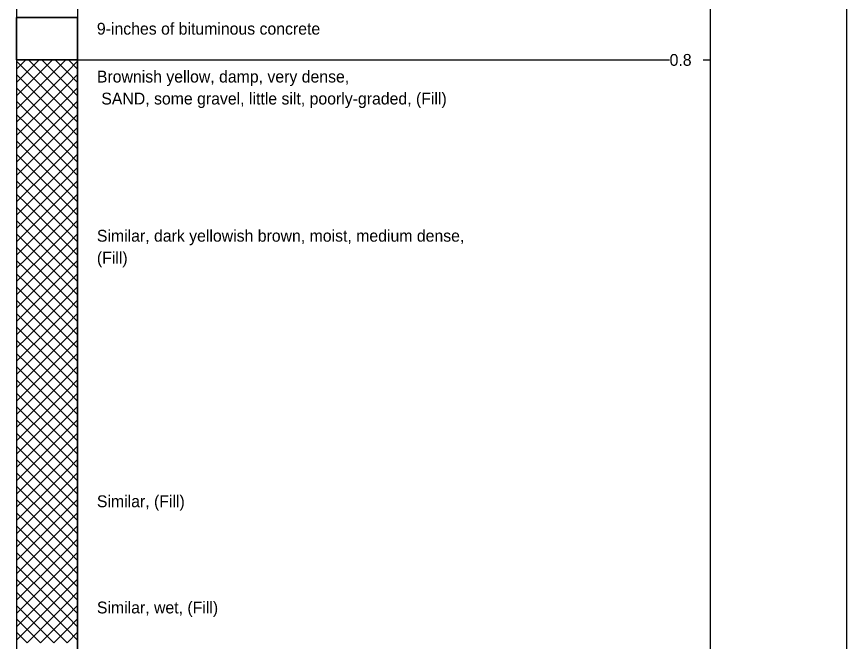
# Model space of a CAD drawing. Extents: x 9422 to 9552, y 6780 to 6860.
# Drawn here: x 9438.31 to 9453.95, y 6835.26 to 6847.03 of the extents above; entities that cross this region are included whole.
import ezdxf

# ---------------------------------------------------------------- set-up
doc = ezdxf.new("R2010")
doc.units = 0
doc.layers.add('7', color=7, linetype='Continuous')
doc.layers.add('8', color=7, linetype='Continuous')

msp = doc.modelspace()

# ---------------------------------------------------------------- linework, layer by layer
at = {"layer": '7'}
for p, q in [((9438.314, 6847.011), (9438.314, 6846.211)), ((9439.463, 6847.011), (9438.314, 6847.011)), ((9439.463, 6846.211), (9439.463, 6847.011)), ((9438.314, 6846.211), (9439.463, 6846.211)), ((9438.314, 6846.211), (9438.314, 6834.011)), ((9439.463, 6846.211), (9438.314, 6846.211)), ((9439.463, 6834.011), (9439.463, 6846.211)), ((9439.463, 6846.211), (9450.615, 6846.211)), ((9451.244, 6846.211), (9451.38, 6846.211))]:
    msp.add_line(p, q, dxfattribs=at)
for points in [[(9453.945, 6860.114), (9453.945, 6821.983)], [(9438.314, 6850.528), (9438.314, 6821.983)], [(9439.463, 6850.528), (9439.463, 6821.983)], [(9451.38, 6850.528), (9451.38, 6821.983)]]:
    msp.add_lwpolyline(points, dxfattribs=at)
at = {"layer": '8'}
for p, q in [((9438.314, 6846.036), (9438.489, 6846.211)), ((9438.514, 6845.986), (9438.314, 6846.185)), ((9438.514, 6845.986), (9438.739, 6846.211)), ((9438.764, 6845.986), (9438.539, 6846.211)), ((9438.764, 6845.986), (9438.989, 6846.211)), ((9439.014, 6845.986), (9438.789, 6846.211)), ((9439.014, 6845.986), (9439.239, 6846.211)), ((9439.264, 6845.986), (9439.039, 6846.211)), ((9439.264, 6845.986), (9439.463, 6846.185)), ((9439.463, 6846.036), (9439.289, 6846.211)), ((9438.314, 6845.786), (9438.514, 6845.986)), ((9438.764, 6845.736), (9438.514, 6845.986)), ((9438.514, 6845.736), (9438.764, 6845.986)), ((9439.014, 6845.736), (9438.764, 6845.986)), ((9438.764, 6845.736), (9439.014, 6845.986)), ((9439.264, 6845.736), (9439.014, 6845.986)), ((9439.014, 6845.736), (9439.264, 6845.986)), ((9439.463, 6845.786), (9439.264, 6845.986)), ((9438.514, 6845.736), (9438.314, 6845.935)), ((9439.264, 6845.736), (9439.463, 6845.935)), ((9438.314, 6845.536), (9438.514, 6845.736)), ((9438.514, 6845.486), (9438.314, 6845.685)), ((9438.764, 6845.486), (9438.514, 6845.736)), ((9438.514, 6845.486), (9438.764, 6845.736)), ((9439.014, 6845.486), (9438.764, 6845.736)), ((9438.764, 6845.486), (9439.014, 6845.736)), ((9439.264, 6845.486), (9439.014, 6845.736)), ((9439.014, 6845.486), (9439.264, 6845.736)), ((9439.463, 6845.536), (9439.264, 6845.736)), ((9439.264, 6845.486), (9439.463, 6845.685)), ((9438.314, 6845.286), (9438.514, 6845.486)), ((9438.514, 6845.236), (9438.314, 6845.435)), ((9438.764, 6845.236), (9438.514, 6845.486)), ((9438.514, 6845.236), (9438.764, 6845.486)), ((9439.014, 6845.236), (9438.764, 6845.486)), ((9438.764, 6845.236), (9439.014, 6845.486)), ((9439.264, 6845.236), (9439.014, 6845.486)), ((9439.014, 6845.236), (9439.264, 6845.486)), ((9439.463, 6845.286), (9439.264, 6845.486)), ((9439.264, 6845.236), (9439.463, 6845.435)), ((9438.314, 6845.036), (9438.514, 6845.236)), ((9438.514, 6844.986), (9438.314, 6845.185)), ((9438.764, 6844.986), (9438.514, 6845.236)), ((9438.514, 6844.986), (9438.764, 6845.236)), ((9439.014, 6844.986), (9438.764, 6845.236)), ((9438.764, 6844.986), (9439.014, 6845.236)), ((9439.264, 6844.986), (9439.014, 6845.236)), ((9439.014, 6844.986), (9439.264, 6845.236)), ((9439.463, 6845.036), (9439.264, 6845.236)), ((9439.264, 6844.986), (9439.463, 6845.185)), ((9438.314, 6844.786), (9438.514, 6844.986)), ((9438.514, 6844.736), (9438.314, 6844.935)), ((9438.764, 6844.736), (9438.514, 6844.986)), ((9438.514, 6844.736), (9438.764, 6844.986)), ((9439.014, 6844.736), (9438.764, 6844.986)), ((9438.764, 6844.736), (9439.014, 6844.986)), ((9439.264, 6844.736), (9439.014, 6844.986)), ((9439.014, 6844.736), (9439.264, 6844.986)), ((9439.463, 6844.786), (9439.264, 6844.986)), ((9439.264, 6844.736), (9439.463, 6844.935)), ((9438.314, 6844.536), (9438.514, 6844.736)), ((9438.764, 6844.486), (9438.514, 6844.736)), ((9438.514, 6844.486), (9438.764, 6844.736)), ((9439.014, 6844.486), (9438.764, 6844.736)), ((9438.764, 6844.486), (9439.014, 6844.736)), ((9439.264, 6844.486), (9439.014, 6844.736)), ((9439.014, 6844.486), (9439.264, 6844.736)), ((9439.463, 6844.536), (9439.264, 6844.736)), ((9438.514, 6844.486), (9438.314, 6844.685)), ((9439.264, 6844.486), (9439.463, 6844.685)), ((9438.314, 6844.286), (9438.514, 6844.486)), ((9438.514, 6844.236), (9438.314, 6844.435)), ((9438.764, 6844.236), (9438.514, 6844.486)), ((9438.514, 6844.236), (9438.764, 6844.486)), ((9439.014, 6844.236), (9438.764, 6844.486)), ((9438.764, 6844.236), (9439.014, 6844.486)), ((9439.264, 6844.236), (9439.014, 6844.486)), ((9439.014, 6844.236), (9439.264, 6844.486)), ((9439.463, 6844.286), (9439.264, 6844.486)), ((9439.264, 6844.236), (9439.463, 6844.435)), ((9438.314, 6844.036), (9438.514, 6844.236)), ((9438.514, 6843.986), (9438.314, 6844.185)), ((9438.764, 6843.986), (9438.514, 6844.236)), ((9438.514, 6843.986), (9438.764, 6844.236)), ((9439.014, 6843.986), (9438.764, 6844.236)), ((9438.764, 6843.986), (9439.014, 6844.236)), ((9439.264, 6843.986), (9439.014, 6844.236)), ((9439.014, 6843.986), (9439.264, 6844.236)), ((9439.463, 6844.036), (9439.264, 6844.236)), ((9439.264, 6843.986), (9439.463, 6844.185)), ((9438.314, 6843.786), (9438.514, 6843.986)), ((9438.514, 6843.736), (9438.314, 6843.935)), ((9438.764, 6843.736), (9438.514, 6843.986)), ((9438.514, 6843.736), (9438.764, 6843.986)), ((9439.014, 6843.736), (9438.764, 6843.986)), ((9438.764, 6843.736), (9439.014, 6843.986)), ((9439.264, 6843.736), (9439.014, 6843.986)), ((9439.014, 6843.736), (9439.264, 6843.986)), ((9439.463, 6843.786), (9439.264, 6843.986)), ((9439.264, 6843.736), (9439.463, 6843.935)), ((9438.314, 6843.536), (9438.514, 6843.736)), ((9438.514, 6843.486), (9438.314, 6843.685)), ((9438.764, 6843.486), (9438.514, 6843.736)), ((9438.514, 6843.486), (9438.764, 6843.736)), ((9439.014, 6843.486), (9438.764, 6843.736)), ((9438.764, 6843.486), (9439.014, 6843.736)), ((9439.264, 6843.486), (9439.014, 6843.736)), ((9439.014, 6843.486), (9439.264, 6843.736)), ((9439.463, 6843.536), (9439.264, 6843.736)), ((9439.264, 6843.486), (9439.463, 6843.685)), ((9438.314, 6843.286), (9438.514, 6843.486)), ((9438.764, 6843.236), (9438.514, 6843.486)), ((9438.514, 6843.236), (9438.764, 6843.486)), ((9439.014, 6843.236), (9438.764, 6843.486)), ((9438.764, 6843.236), (9439.014, 6843.486)), ((9439.264, 6843.236), (9439.014, 6843.486)), ((9439.014, 6843.236), (9439.264, 6843.486)), ((9439.463, 6843.286), (9439.264, 6843.486)), ((9438.514, 6843.236), (9438.314, 6843.435)), ((9439.264, 6843.236), (9439.463, 6843.435)), ((9438.314, 6843.036), (9438.514, 6843.236)), ((9438.514, 6842.986), (9438.314, 6843.185)), ((9438.764, 6842.986), (9438.514, 6843.236)), ((9438.514, 6842.986), (9438.764, 6843.236)), ((9439.014, 6842.986), (9438.764, 6843.236)), ((9438.764, 6842.986), (9439.014, 6843.236)), ((9439.264, 6842.986), (9439.014, 6843.236)), ((9439.014, 6842.986), (9439.264, 6843.236)), ((9439.463, 6843.036), (9439.264, 6843.236)), ((9439.264, 6842.986), (9439.463, 6843.185)), ((9438.314, 6842.786), (9438.514, 6842.986)), ((9438.514, 6842.736), (9438.314, 6842.935)), ((9438.764, 6842.736), (9438.514, 6842.986)), ((9438.514, 6842.736), (9438.764, 6842.986)), ((9439.014, 6842.736), (9438.764, 6842.986)), ((9438.764, 6842.736), (9439.014, 6842.986)), ((9439.264, 6842.736), (9439.014, 6842.986)), ((9439.014, 6842.736), (9439.264, 6842.986)), ((9439.463, 6842.786), (9439.264, 6842.986)), ((9439.264, 6842.736), (9439.463, 6842.935)), ((9438.314, 6842.536), (9438.514, 6842.736)), ((9438.514, 6842.486), (9438.314, 6842.685)), ((9438.764, 6842.486), (9438.514, 6842.736)), ((9438.514, 6842.486), (9438.764, 6842.736)), ((9439.014, 6842.486), (9438.764, 6842.736)), ((9438.764, 6842.486), (9439.014, 6842.736)), ((9439.264, 6842.486), (9439.014, 6842.736)), ((9439.014, 6842.486), (9439.264, 6842.736)), ((9439.463, 6842.536), (9439.264, 6842.736)), ((9439.264, 6842.486), (9439.463, 6842.685)), ((9438.314, 6842.286), (9438.514, 6842.486)), ((9438.514, 6842.236), (9438.314, 6842.435)), ((9438.764, 6842.236), (9438.514, 6842.486)), ((9438.514, 6842.236), (9438.764, 6842.486)), ((9439.014, 6842.236), (9438.764, 6842.486)), ((9438.764, 6842.236), (9439.014, 6842.486)), ((9439.264, 6842.236), (9439.014, 6842.486)), ((9439.014, 6842.236), (9439.264, 6842.486)), ((9439.463, 6842.286), (9439.264, 6842.486)), ((9439.264, 6842.236), (9439.463, 6842.435)), ((9438.314, 6842.036), (9438.514, 6842.236)), ((9438.764, 6841.986), (9438.514, 6842.236)), ((9438.514, 6841.986), (9438.764, 6842.236)), ((9439.014, 6841.986), (9438.764, 6842.236)), ((9438.764, 6841.986), (9439.014, 6842.236)), ((9439.264, 6841.986), (9439.014, 6842.236)), ((9439.014, 6841.986), (9439.264, 6842.236)), ((9439.463, 6842.036), (9439.264, 6842.236)), ((9438.514, 6841.986), (9438.314, 6842.185)), ((9439.264, 6841.986), (9439.463, 6842.185)), ((9438.314, 6841.786), (9438.514, 6841.986)), ((9438.514, 6841.736), (9438.314, 6841.935)), ((9438.764, 6841.736), (9438.514, 6841.986)), ((9438.514, 6841.736), (9438.764, 6841.986)), ((9439.014, 6841.736), (9438.764, 6841.986)), ((9438.764, 6841.736), (9439.014, 6841.986)), ((9439.264, 6841.736), (9439.014, 6841.986)), ((9439.014, 6841.736), (9439.264, 6841.986)), ((9439.463, 6841.786), (9439.264, 6841.986)), ((9439.264, 6841.736), (9439.463, 6841.935)), ((9438.314, 6841.536), (9438.514, 6841.736)), ((9438.514, 6841.486), (9438.314, 6841.685)), ((9438.764, 6841.486), (9438.514, 6841.736)), ((9438.514, 6841.486), (9438.764, 6841.736)), ((9439.014, 6841.486), (9438.764, 6841.736)), ((9438.764, 6841.486), (9439.014, 6841.736)), ((9439.264, 6841.486), (9439.014, 6841.736)), ((9439.014, 6841.486), (9439.264, 6841.736)), ((9439.463, 6841.536), (9439.264, 6841.736)), ((9439.264, 6841.486), (9439.463, 6841.685)), ((9438.314, 6841.286), (9438.514, 6841.486)), ((9438.514, 6841.236), (9438.314, 6841.435)), ((9438.764, 6841.236), (9438.514, 6841.486)), ((9438.514, 6841.236), (9438.764, 6841.486)), ((9439.014, 6841.236), (9438.764, 6841.486)), ((9438.764, 6841.236), (9439.014, 6841.486)), ((9439.264, 6841.236), (9439.014, 6841.486)), ((9439.014, 6841.236), (9439.264, 6841.486)), ((9439.463, 6841.286), (9439.264, 6841.486)), ((9439.264, 6841.236), (9439.463, 6841.435)), ((9438.314, 6841.036), (9438.514, 6841.236)), ((9438.514, 6840.986), (9438.314, 6841.185)), ((9438.764, 6840.986), (9438.514, 6841.236)), ((9438.514, 6840.986), (9438.764, 6841.236)), ((9439.014, 6840.986), (9438.764, 6841.236)), ((9438.764, 6840.986), (9439.014, 6841.236)), ((9439.264, 6840.986), (9439.014, 6841.236)), ((9439.014, 6840.986), (9439.264, 6841.236)), ((9439.463, 6841.036), (9439.264, 6841.236)), ((9439.264, 6840.986), (9439.463, 6841.185)), ((9438.314, 6840.786), (9438.514, 6840.986)), ((9438.764, 6840.736), (9438.514, 6840.986)), ((9438.514, 6840.736), (9438.764, 6840.986)), ((9439.014, 6840.736), (9438.764, 6840.986)), ((9438.764, 6840.736), (9439.014, 6840.986)), ((9439.264, 6840.736), (9439.014, 6840.986)), ((9439.014, 6840.736), (9439.264, 6840.986)), ((9439.463, 6840.786), (9439.264, 6840.986)), ((9438.514, 6840.736), (9438.314, 6840.935)), ((9439.264, 6840.736), (9439.463, 6840.935)), ((9438.314, 6840.536), (9438.514, 6840.736)), ((9438.514, 6840.486), (9438.314, 6840.685)), ((9438.764, 6840.486), (9438.514, 6840.736)), ((9438.514, 6840.486), (9438.764, 6840.736)), ((9439.014, 6840.486), (9438.764, 6840.736)), ((9438.764, 6840.486), (9439.014, 6840.736)), ((9439.264, 6840.486), (9439.014, 6840.736)), ((9439.014, 6840.486), (9439.264, 6840.736)), ((9439.463, 6840.536), (9439.264, 6840.736)), ((9439.264, 6840.486), (9439.463, 6840.685)), ((9438.314, 6840.286), (9438.514, 6840.486)), ((9438.514, 6840.236), (9438.314, 6840.435)), ((9438.764, 6840.236), (9438.514, 6840.486)), ((9438.514, 6840.236), (9438.764, 6840.486)), ((9439.014, 6840.236), (9438.764, 6840.486)), ((9438.764, 6840.236), (9439.014, 6840.486)), ((9439.264, 6840.236), (9439.014, 6840.486)), ((9439.014, 6840.236), (9439.264, 6840.486)), ((9439.463, 6840.286), (9439.264, 6840.486)), ((9439.264, 6840.236), (9439.463, 6840.435)), ((9438.314, 6840.036), (9438.514, 6840.236)), ((9438.514, 6839.986), (9438.314, 6840.185)), ((9438.764, 6839.986), (9438.514, 6840.236)), ((9438.514, 6839.986), (9438.764, 6840.236)), ((9439.014, 6839.986), (9438.764, 6840.236)), ((9438.764, 6839.986), (9439.014, 6840.236)), ((9439.264, 6839.986), (9439.014, 6840.236)), ((9439.014, 6839.986), (9439.264, 6840.236)), ((9439.463, 6840.036), (9439.264, 6840.236)), ((9439.264, 6839.986), (9439.463, 6840.185)), ((9438.314, 6839.786), (9438.514, 6839.986)), ((9438.514, 6839.736), (9438.314, 6839.935)), ((9438.764, 6839.736), (9438.514, 6839.986)), ((9438.514, 6839.736), (9438.764, 6839.986)), ((9439.014, 6839.736), (9438.764, 6839.986)), ((9438.764, 6839.736), (9439.014, 6839.986)), ((9439.264, 6839.736), (9439.014, 6839.986)), ((9439.014, 6839.736), (9439.264, 6839.986)), ((9439.463, 6839.786), (9439.264, 6839.986)), ((9439.264, 6839.736), (9439.463, 6839.935)), ((9438.314, 6839.536), (9438.514, 6839.736)), ((9438.764, 6839.486), (9438.514, 6839.736)), ((9438.514, 6839.486), (9438.764, 6839.736)), ((9439.014, 6839.486), (9438.764, 6839.736)), ((9438.764, 6839.486), (9439.014, 6839.736)), ((9439.264, 6839.486), (9439.014, 6839.736)), ((9439.014, 6839.486), (9439.264, 6839.736)), ((9439.463, 6839.536), (9439.264, 6839.736)), ((9438.514, 6839.486), (9438.314, 6839.685)), ((9439.264, 6839.486), (9439.463, 6839.685)), ((9438.314, 6839.286), (9438.514, 6839.486)), ((9438.514, 6839.236), (9438.314, 6839.435)), ((9438.764, 6839.236), (9438.514, 6839.486)), ((9438.514, 6839.236), (9438.764, 6839.486)), ((9439.014, 6839.236), (9438.764, 6839.486)), ((9438.764, 6839.236), (9439.014, 6839.486)), ((9439.264, 6839.236), (9439.014, 6839.486)), ((9439.014, 6839.236), (9439.264, 6839.486)), ((9439.463, 6839.286), (9439.264, 6839.486)), ((9439.264, 6839.236), (9439.463, 6839.435)), ((9438.314, 6839.036), (9438.514, 6839.236)), ((9438.514, 6838.986), (9438.314, 6839.185)), ((9438.764, 6838.986), (9438.514, 6839.236)), ((9438.514, 6838.986), (9438.764, 6839.236)), ((9439.014, 6838.986), (9438.764, 6839.236)), ((9438.764, 6838.986), (9439.014, 6839.236)), ((9439.264, 6838.986), (9439.014, 6839.236)), ((9439.014, 6838.986), (9439.264, 6839.236)), ((9439.463, 6839.036), (9439.264, 6839.236)), ((9439.264, 6838.986), (9439.463, 6839.185)), ((9438.314, 6838.786), (9438.514, 6838.986)), ((9438.514, 6838.736), (9438.314, 6838.935)), ((9438.764, 6838.736), (9438.514, 6838.986)), ((9438.514, 6838.736), (9438.764, 6838.986)), ((9439.014, 6838.736), (9438.764, 6838.986)), ((9438.764, 6838.736), (9439.014, 6838.986)), ((9439.264, 6838.736), (9439.014, 6838.986)), ((9439.014, 6838.736), (9439.264, 6838.986)), ((9439.463, 6838.786), (9439.264, 6838.986)), ((9439.264, 6838.736), (9439.463, 6838.935)), ((9438.314, 6838.536), (9438.514, 6838.736)), ((9438.514, 6838.486), (9438.314, 6838.685)), ((9438.764, 6838.486), (9438.514, 6838.736)), ((9438.514, 6838.486), (9438.764, 6838.736)), ((9439.014, 6838.486), (9438.764, 6838.736)), ((9438.764, 6838.486), (9439.014, 6838.736)), ((9439.264, 6838.486), (9439.014, 6838.736)), ((9439.014, 6838.486), (9439.264, 6838.736)), ((9439.463, 6838.536), (9439.264, 6838.736)), ((9439.264, 6838.486), (9439.463, 6838.685)), ((9438.314, 6838.286), (9438.514, 6838.486)), ((9438.764, 6838.236), (9438.514, 6838.486)), ((9438.514, 6838.236), (9438.764, 6838.486)), ((9439.014, 6838.236), (9438.764, 6838.486)), ((9438.764, 6838.236), (9439.014, 6838.486)), ((9439.264, 6838.236), (9439.014, 6838.486)), ((9439.014, 6838.236), (9439.264, 6838.486)), ((9439.463, 6838.286), (9439.264, 6838.486)), ((9438.514, 6838.236), (9438.314, 6838.435)), ((9439.264, 6838.236), (9439.463, 6838.435)), ((9438.314, 6838.036), (9438.514, 6838.236)), ((9438.514, 6837.986), (9438.314, 6838.185)), ((9438.764, 6837.986), (9438.514, 6838.236)), ((9438.514, 6837.986), (9438.764, 6838.236)), ((9439.014, 6837.986), (9438.764, 6838.236)), ((9438.764, 6837.986), (9439.014, 6838.236)), ((9439.264, 6837.986), (9439.014, 6838.236)), ((9439.014, 6837.986), (9439.264, 6838.236)), ((9439.463, 6838.036), (9439.264, 6838.236)), ((9439.264, 6837.986), (9439.463, 6838.185)), ((9438.314, 6837.786), (9438.514, 6837.986)), ((9438.514, 6837.736), (9438.314, 6837.935)), ((9438.764, 6837.736), (9438.514, 6837.986)), ((9438.514, 6837.736), (9438.764, 6837.986)), ((9439.014, 6837.736), (9438.764, 6837.986)), ((9438.764, 6837.736), (9439.014, 6837.986)), ((9439.264, 6837.736), (9439.014, 6837.986)), ((9439.014, 6837.736), (9439.264, 6837.986)), ((9439.463, 6837.786), (9439.264, 6837.986)), ((9439.264, 6837.736), (9439.463, 6837.935)), ((9438.314, 6837.536), (9438.514, 6837.736)), ((9438.514, 6837.486), (9438.314, 6837.685)), ((9438.764, 6837.486), (9438.514, 6837.736)), ((9438.514, 6837.486), (9438.764, 6837.736)), ((9439.014, 6837.486), (9438.764, 6837.736)), ((9438.764, 6837.486), (9439.014, 6837.736)), ((9439.264, 6837.486), (9439.014, 6837.736)), ((9439.014, 6837.486), (9439.264, 6837.736)), ((9439.463, 6837.536), (9439.264, 6837.736)), ((9439.264, 6837.486), (9439.463, 6837.685)), ((9438.314, 6837.286), (9438.514, 6837.486)), ((9438.514, 6837.236), (9438.314, 6837.435)), ((9438.764, 6837.236), (9438.514, 6837.486)), ((9438.514, 6837.236), (9438.764, 6837.486)), ((9439.014, 6837.236), (9438.764, 6837.486)), ((9438.764, 6837.236), (9439.014, 6837.486)), ((9439.264, 6837.236), (9439.014, 6837.486)), ((9439.014, 6837.236), (9439.264, 6837.486)), ((9439.463, 6837.286), (9439.264, 6837.486)), ((9439.264, 6837.236), (9439.463, 6837.435)), ((9438.314, 6837.036), (9438.514, 6837.236)), ((9438.764, 6836.986), (9438.514, 6837.236)), ((9438.514, 6836.986), (9438.764, 6837.236)), ((9439.014, 6836.986), (9438.764, 6837.236)), ((9438.764, 6836.986), (9439.014, 6837.236)), ((9439.264, 6836.986), (9439.014, 6837.236)), ((9439.014, 6836.986), (9439.264, 6837.236)), ((9439.463, 6837.036), (9439.264, 6837.236)), ((9438.514, 6836.986), (9438.314, 6837.185)), ((9439.264, 6836.986), (9439.463, 6837.185)), ((9438.314, 6836.786), (9438.514, 6836.986)), ((9438.514, 6836.736), (9438.314, 6836.935)), ((9438.764, 6836.736), (9438.514, 6836.986)), ((9438.514, 6836.736), (9438.764, 6836.986)), ((9439.014, 6836.736), (9438.764, 6836.986)), ((9438.764, 6836.736), (9439.014, 6836.986)), ((9439.264, 6836.736), (9439.014, 6836.986)), ((9439.014, 6836.736), (9439.264, 6836.986)), ((9439.463, 6836.786), (9439.264, 6836.986)), ((9439.264, 6836.736), (9439.463, 6836.935)), ((9438.314, 6836.536), (9438.514, 6836.736)), ((9438.514, 6836.486), (9438.314, 6836.685)), ((9438.764, 6836.486), (9438.514, 6836.736)), ((9438.514, 6836.486), (9438.764, 6836.736)), ((9439.014, 6836.486), (9438.764, 6836.736)), ((9438.764, 6836.486), (9439.014, 6836.736)), ((9439.264, 6836.486), (9439.014, 6836.736)), ((9439.014, 6836.486), (9439.264, 6836.736)), ((9439.463, 6836.536), (9439.264, 6836.736)), ((9439.264, 6836.486), (9439.463, 6836.685)), ((9438.314, 6836.286), (9438.514, 6836.486)), ((9438.514, 6836.236), (9438.314, 6836.435)), ((9438.764, 6836.236), (9438.514, 6836.486)), ((9438.514, 6836.236), (9438.764, 6836.486)), ((9439.014, 6836.236), (9438.764, 6836.486)), ((9438.764, 6836.236), (9439.014, 6836.486)), ((9439.264, 6836.236), (9439.014, 6836.486)), ((9439.014, 6836.236), (9439.264, 6836.486)), ((9439.463, 6836.286), (9439.264, 6836.486)), ((9439.264, 6836.236), (9439.463, 6836.435)), ((9438.314, 6836.036), (9438.514, 6836.236)), ((9438.514, 6835.986), (9438.314, 6836.185)), ((9438.764, 6835.986), (9438.514, 6836.236)), ((9438.514, 6835.986), (9438.764, 6836.236)), ((9439.014, 6835.986), (9438.764, 6836.236)), ((9438.764, 6835.986), (9439.014, 6836.236)), ((9439.264, 6835.986), (9439.014, 6836.236)), ((9439.014, 6835.986), (9439.264, 6836.236)), ((9439.463, 6836.036), (9439.264, 6836.236)), ((9439.264, 6835.986), (9439.463, 6836.185)), ((9438.314, 6835.786), (9438.514, 6835.986)), ((9438.764, 6835.736), (9438.514, 6835.986)), ((9438.514, 6835.736), (9438.764, 6835.986)), ((9439.014, 6835.736), (9438.764, 6835.986)), ((9438.764, 6835.736), (9439.014, 6835.986)), ((9439.264, 6835.736), (9439.014, 6835.986)), ((9439.014, 6835.736), (9439.264, 6835.986)), ((9439.463, 6835.786), (9439.264, 6835.986)), ((9438.514, 6835.736), (9438.314, 6835.935)), ((9439.264, 6835.736), (9439.463, 6835.935)), ((9438.314, 6835.536), (9438.514, 6835.736)), ((9438.514, 6835.486), (9438.314, 6835.685)), ((9438.764, 6835.486), (9438.514, 6835.736)), ((9438.514, 6835.486), (9438.764, 6835.736)), ((9439.014, 6835.486), (9438.764, 6835.736)), ((9438.764, 6835.486), (9439.014, 6835.736)), ((9439.264, 6835.486), (9439.014, 6835.736)), ((9439.014, 6835.486), (9439.264, 6835.736)), ((9439.463, 6835.536), (9439.264, 6835.736)), ((9439.264, 6835.486), (9439.463, 6835.685)), ((9438.314, 6835.286), (9438.514, 6835.486)), ((9438.514, 6835.236), (9438.314, 6835.435)), ((9438.764, 6835.236), (9438.514, 6835.486)), ((9438.514, 6835.236), (9438.764, 6835.486)), ((9439.014, 6835.236), (9438.764, 6835.486)), ((9438.764, 6835.236), (9439.014, 6835.486)), ((9439.264, 6835.236), (9439.014, 6835.486)), ((9439.014, 6835.236), (9439.264, 6835.486)), ((9439.463, 6835.286), (9439.264, 6835.486)), ((9439.264, 6835.236), (9439.463, 6835.435))]:
    msp.add_line(p, q, dxfattribs=at)
msp.add_lwpolyline([(9439.463, 6847.011), (9439.463, 6846.211), (9438.314, 6846.211), (9438.314, 6847.011)], close=True, dxfattribs=at)

# ---------------------------------------------------------------- texts
at = {"layer": '7'}
for s, p in [('9-inches of bituminous concrete', (9439.827, 6846.687)), ('0.8', (9450.615, 6846.099)), ('Brownish yellow, damp, very dense,', (9439.827, 6845.785)), (' SAND, some gravel, little silt, poorly-graded, (Fill)', (9439.827, 6845.371)), ('Similar, dark yellowish brown, moist, medium dense,', (9439.827, 6842.788)), ('(Fill)', (9439.827, 6842.374)), ('Similar, (Fill)', (9439.827, 6837.788)), ('Similar, wet, (Fill)', (9439.827, 6835.788))]:
    msp.add_text(s, height=0.2228, dxfattribs=at).set_placement(p)

doc.saveas('drawing.dxf')
